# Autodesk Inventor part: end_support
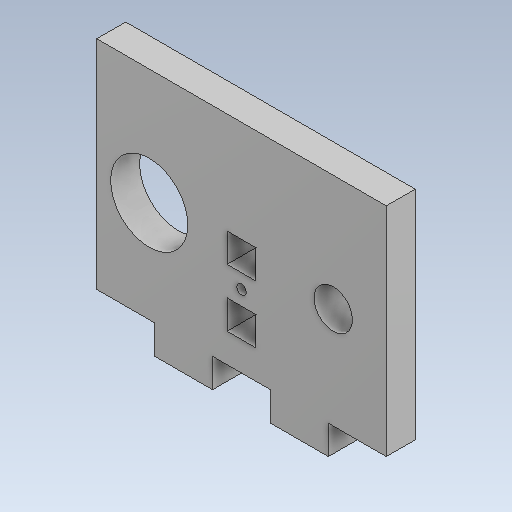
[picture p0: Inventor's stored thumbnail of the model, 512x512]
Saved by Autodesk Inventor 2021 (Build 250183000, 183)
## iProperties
Created: 2026-10
Part Number: end_support
Material: Steel
Document SubType Name: Modeling
Designer: hp
Density: 7.85 g/cm^3
Appearance: Default
Author: hp
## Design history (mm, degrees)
feature "Body1"
body "Solid1"
